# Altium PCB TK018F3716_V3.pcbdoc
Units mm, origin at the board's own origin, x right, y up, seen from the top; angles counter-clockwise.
Board outline 35.7 x 43.6 mm, 2 copper layers (Top Layer, Bottom Layer), stack 1.58 mm thick; 15 components, 14 nets, 81 pads, 72 vias.
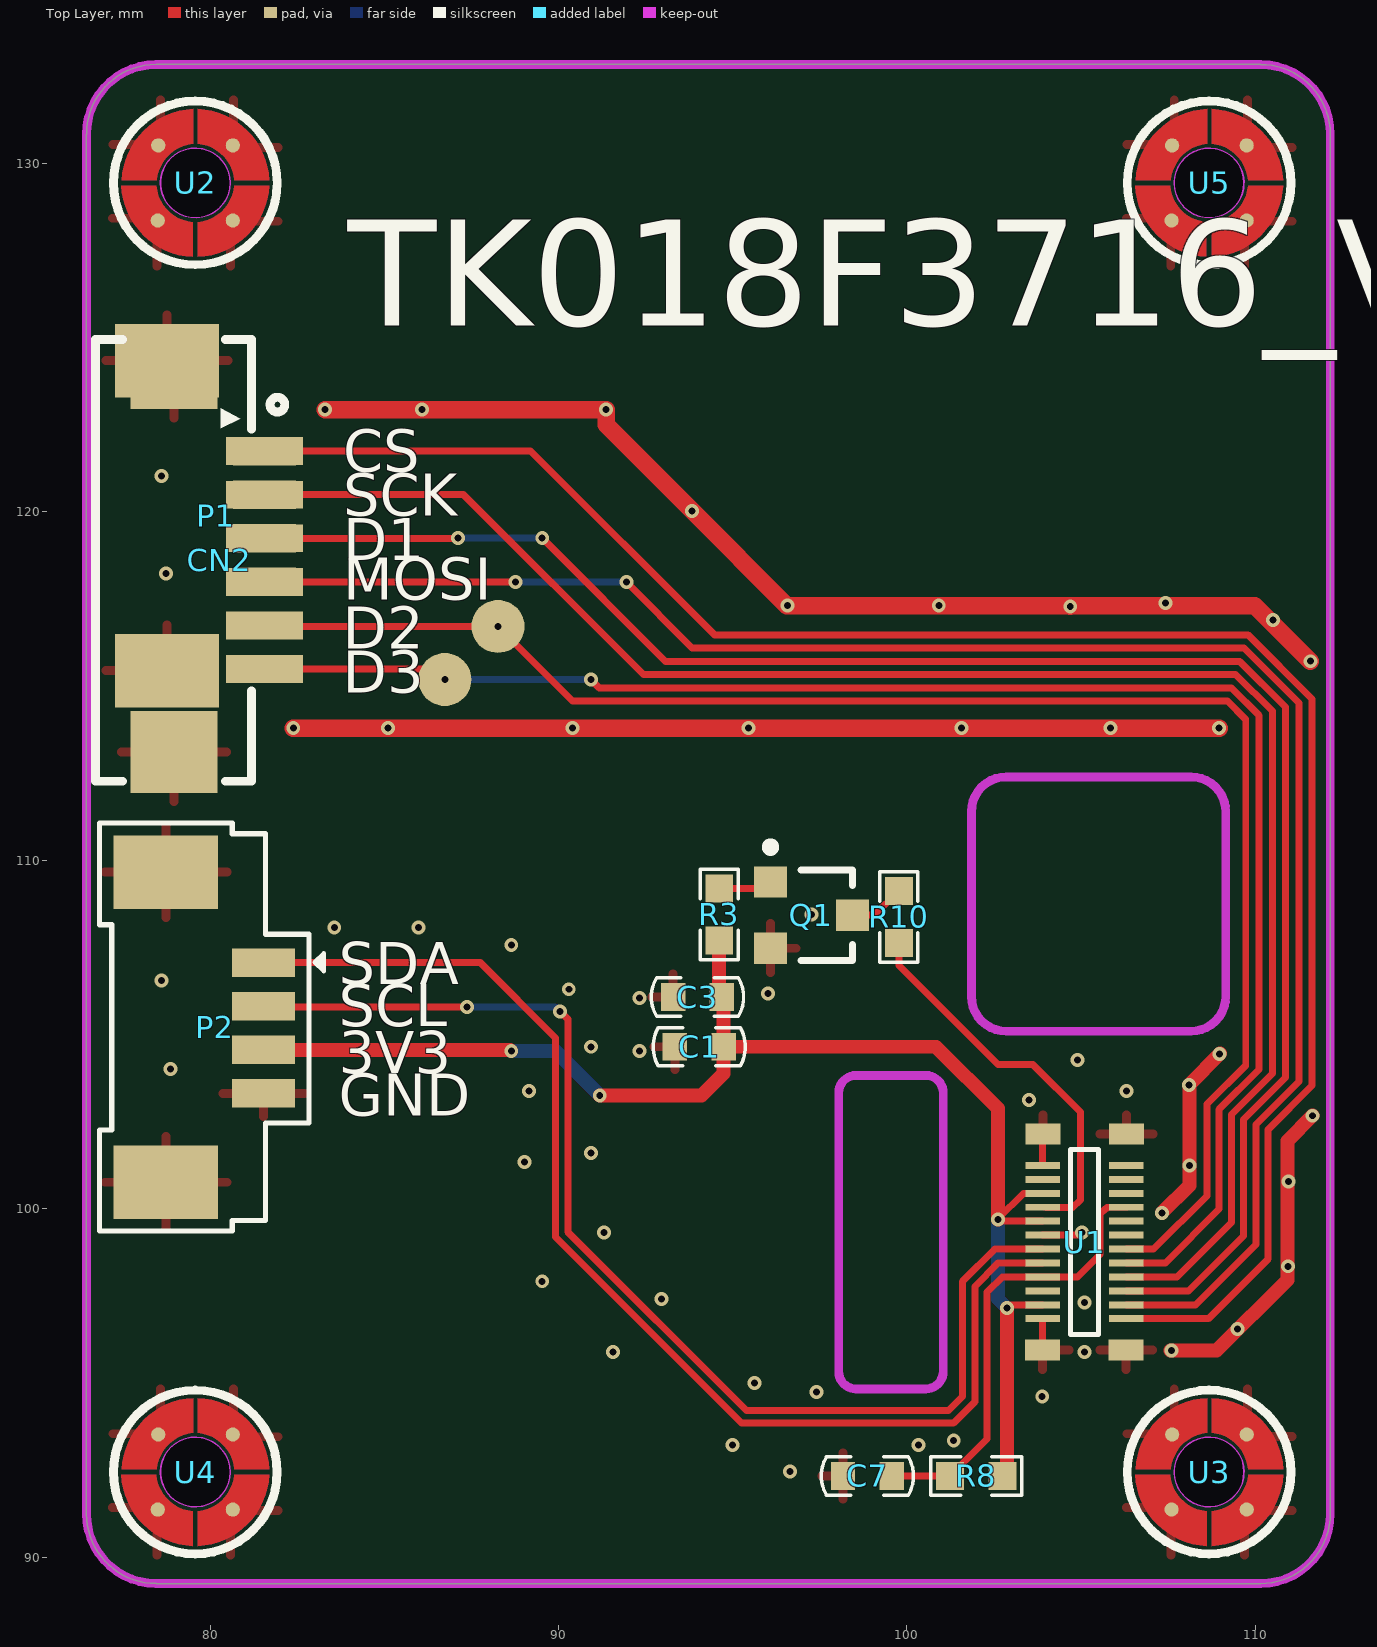
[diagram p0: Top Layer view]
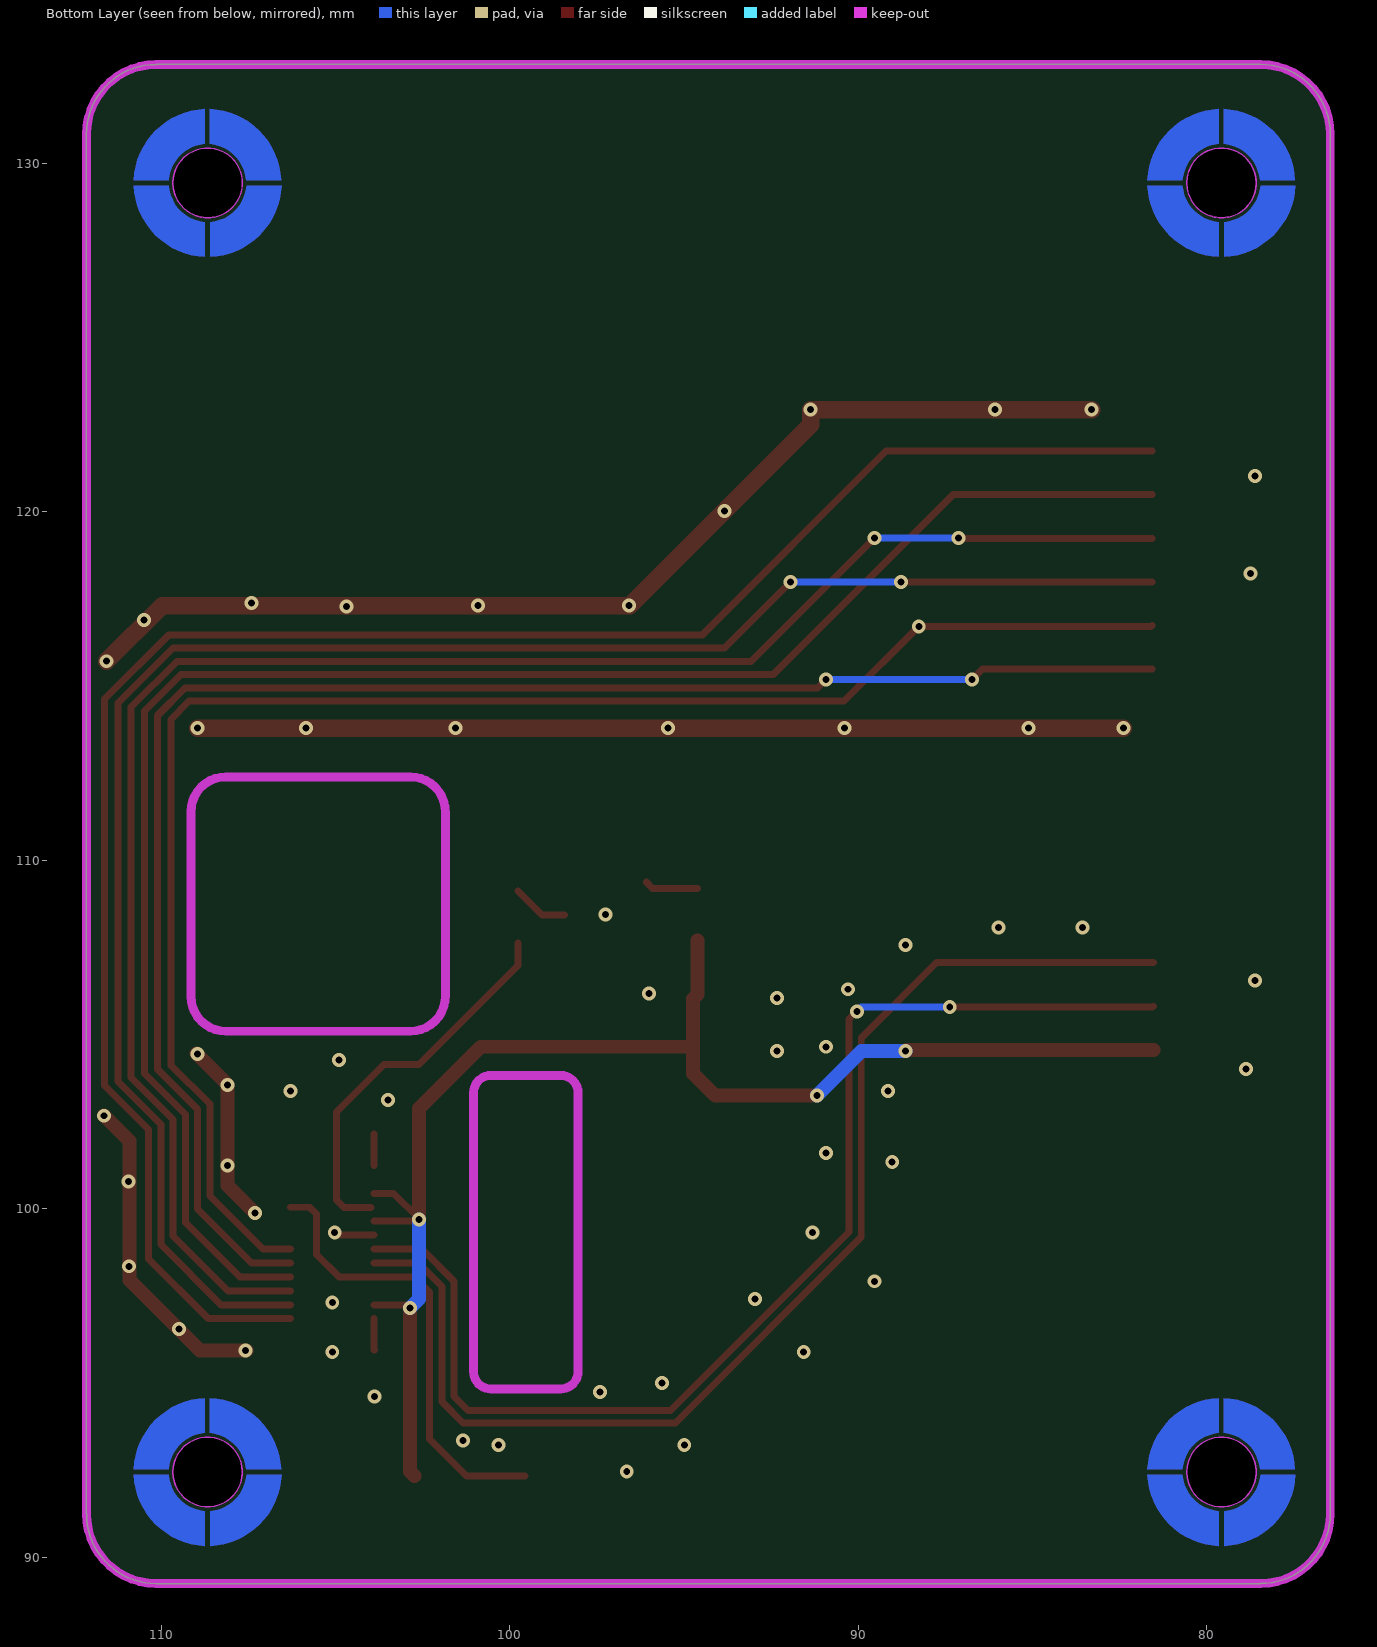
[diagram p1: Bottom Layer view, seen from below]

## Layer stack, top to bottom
Top Solder Mask Layer: solder mask 0.01, Dk 3.3
Top Layer: signal copper 0.035
Dielectric1: surface 1.51, FR4, Dk 4.5
Bottom Layer: signal copper 0.035
Bottom Solder Mask Layer: solder mask 0.01, Dk 3.3

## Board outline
78.454,132.842 ccw(c78.454,130.842) 76.454,130.842 76.454,91.242 ccw(c78.454,91.242) 78.454,89.242 110.154,89.242 ccw(c110.154,91.242) 112.154,91.242 112.154,130.842 ccw(c110.154,130.842) 110.154,132.842 78.454,132.842

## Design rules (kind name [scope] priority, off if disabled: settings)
BoardOutlineClearance copperThickness1oz [All] p0: genericclearance=0.254 ignorepadtopadclearanceinfootprint=FALSE except(0: Arc-SplitContinuation Track-SplitContinuation SMDPad-SplitContinuation THPad-SplitContinuation Via-SplitContinuation Fill-SplitContinuation Poly-SplitContinuation Region-SplitContinuation Text-SplitContinuation)
BoardOutlineClearance copperThickness2oz [All] p0: genericclearance=0.254 ignorepadtopadclearanceinfootprint=FALSE except(0: Arc-SplitContinuation Track-SplitContinuation SMDPad-SplitContinuation THPad-SplitContinuation Via-SplitContinuation Fill-SplitContinuation Poly-SplitContinuation Region-SplitContinuation Text-SplitContinuation)
BoardOutlineClearance otherClearance [All] p0: genericclearance=0.254 ignorepadtopadclearanceinfootprint=FALSE except(0: Arc-SplitContinuation Track-SplitContinuation SMDPad-SplitContinuation THPad-SplitContinuation Via-SplitContinuation Fill-SplitContinuation Poly-SplitContinuation Region-SplitContinuation Text-SplitContinuation)
Clearance copperThickness1oz [All] p1: gap=0.178 ignorepadtopadclearanceinfootprint=FALSE
Clearance copperThickness2oz [All] p1: gap=0.178 ignorepadtopadclearanceinfootprint=FALSE
Clearance otherClearance [All] p1: gap=0.178 ignorepadtopadclearanceinfootprint=FALSE
DiffPairsRouting differentialPair [All] p1: maxuncoupledlength=10 minlimit=6 maxlimit=Infinity mostfreqgap=6 toplayer_minwidth=5 toplayer_prefwidth=10 toplayer_maxwidth=100 bottomlayer_minwidth=5 bottomlayer_prefwidth=10 bottomlayer_maxwidth=100
PasteMaskExpansion pasteMaskExpansion [All] p1: expansion=0
PlaneConnect innerPlane [All] p1: planeconnectstyle=Relief reliefexpansion=0.508 reliefentries=4 reliefconductorwidth=0.254 reliefairgap=0.254
PolygonConnect copperRegion [All] p1: connectstyle=Relief reliefentries=4 reliefconductorwidth=10 polygonreliefangle="90 Angle" airgapwidth=10
RoutingVias viaSize [All] p1: viastyle="Through Hole" holewidth=7.874 minholewidth=7.874 maxholewidth=248.0314 width=7.874 minwidth=7.874 maxwidth=248.0314
SolderMaskExpansion solderMaskExpansion [IsVia] p1: useseparateexpansions=TRUE expansion=-1000 expansionbottom=-1000
SolderMaskExpansion solderMaskExpansion [All] p2: useseparateexpansions=TRUE expansion=2 expansionbottom=2
Width copperThickness1oz [All] p1: maxlimit=100 minlimit=5 preferedwidth=8
Width copperThickness2oz [All] p1: maxlimit=100 minlimit=8 preferedwidth=10

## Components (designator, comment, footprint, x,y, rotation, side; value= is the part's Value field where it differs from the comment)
C1 "104" C0603-1 94.742,104.648 r180 top
C3 "475" C0603-2 94.69,106.076 r180 top
C7 "104" C0603-1 99.568,92.329 r180 top
CN2 "HC-1.25-6PWT" CONN-SMD_6P-P1.25_HC-1.25-6PWT 80.264,118.618 r270 top
P1 "BHEADSMD1x4" BHEADSMD1x4 81.564,121.743 r90 top
P2 "BHEADSMD1x4" BHEADSMD1x4 81.534,107.061 r90 top
Q1 "SI2302" SOT23A 96.087,109.378 r270 top
R3 "18k" R0603 94.615,107.696 r90 top
R8 "18k" R0603 102.743,92.329 r180 top
R10 "5.1R" R0603 99.77,109.124 r270 top
U1 "" TK014F1246-24P 106.299,96.842 r270 top
U2 "" SMTWEM2 79.627,129.542 r0 top
U3 "" SMTWEM2 108.727,92.542 r0 top
U4 "" SMTWEM2 79.627,92.542 r0 top
U5 "" SMTWEM2 108.727,129.542 r0 top

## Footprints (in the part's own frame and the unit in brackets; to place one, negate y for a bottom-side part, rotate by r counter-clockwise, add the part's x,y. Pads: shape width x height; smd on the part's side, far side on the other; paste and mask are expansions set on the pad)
BHEADSMD1x4 [mil]
  rect 32x71 smd: 1(0,0) 2(-49.21,0) 3(-98.43,0) 4(-147.64,0)
  rect 83x118 smd: 5(102.36,110.24) 6(-248.03,110.24)
C0603-1 [mm]
  rect 0.7x0.8 smd paste+0.102 mask+0.1: 1(0,0) 2(1.4,0)
  silkscreen extent -0.62,-0.55 2.02,0.55
C0603-2 [mm]
  rect 0.7x0.8 smd paste+0.102 mask+0.1: 1(0,0) 2(1.4,0)
  silkscreen extent -0.62,-0.55 2.02,0.55
CONN-SMD_6P-P1.25_HC-1.25-6PWT [mm]
  rect 0.8x2.2 smd paste+0 mask+0.05: 1(-3.125,1.3) 2(-1.875,1.3) 3(-0.625,1.3) 4(0.625,1.3) 5(1.875,1.3) 6(3.125,1.3)
  rect 2.35x2.5 smd paste+0 mask+0.05: 7(-5.505,-1.3) 8(5.505,-1.3)
  silkscreen extent -6.33,-3.56 6.35,1.88
R0603 [mm]
  rect 0.8x0.8 smd paste+0.102 mask+0.1: 1(0,0) 2(1.5,0)
  silkscreen extent -0.55,-0.55 2.05,0.55
SMTWEM2 [mm]
  round 0.409 smd: 2(-1.127,-1.177) 2(-1.112,0.977) 2(1.027,-1.177) 2(1.027,0.977)
  Top Layer region: -2.159,-0.024 -2.14,0.174 -2.104,0.369 -2.049,0.56 -1.978,0.745 -1.889,0.923 -1.785,1.091 -1.665,1.25 -1.531,1.396 -1.385,1.53 -1.226,1.65 -1.057,1.754 -0.88,1.843 -0.695,1.915 -0.504,1.969 -0.309,2.005 -0.111,2.024 -0.111,1.022 -0.26,0.999 -0.404,0.957 -0.542,0.897 -0.671,0.819 -0.788,0.724 -0.887,0.622 -0.972,0.508 -1.043,0.385 -1.098,0.254 -1.136,0.117 -1.157,-0.024 -2.159,-0.024
  Top Layer region: 0.026,2.024 0.224,2.005 0.419,1.969 0.61,1.915 0.795,1.843 0.973,1.754 1.141,1.65 1.3,1.53 1.446,1.396 1.58,1.25 1.7,1.091 1.804,0.923 1.893,0.745 1.965,0.56 2.019,0.369 2.055,0.174 2.074,-0.024 1.072,-0.024 1.049,0.125 1.007,0.27 0.947,0.407 0.869,0.536 0.774,0.654 0.672,0.752 0.558,0.837 0.435,0.908 0.304,0.963 0.167,1.001 0.026,1.022 0.026,2.024
  Top Layer region: -0.126,-2.224 -0.324,-2.205 -0.519,-2.169 -0.71,-2.115 -0.895,-2.043 -1.073,-1.954 -1.241,-1.85 -1.4,-1.73 -1.546,-1.596 -1.68,-1.45 -1.8,-1.291 -1.904,-1.123 -1.993,-0.945 -2.065,-0.76 -2.119,-0.569 -2.155,-0.374 -2.174,-0.176 -1.172,-0.176 -1.149,-0.325 -1.107,-0.47 -1.047,-0.607 -0.969,-0.736 -0.874,-0.854 -0.772,-0.952 -0.658,-1.037 -0.535,-1.108 -0.404,-1.163 -0.267,-1.201 -0.126,-1.222 -0.126,-2.224
  Top Layer region: 2.074,-0.176 2.055,-0.374 2.019,-0.569 1.965,-0.76 1.893,-0.945 1.804,-1.123 1.7,-1.291 1.58,-1.45 1.446,-1.596 1.3,-1.73 1.141,-1.85 0.973,-1.954 0.795,-2.043 0.61,-2.115 0.419,-2.169 0.224,-2.205 0.026,-2.224 0.026,-2.224 0.026,-1.222 0.026,-1.222 0.175,-1.199 0.32,-1.157 0.457,-1.097 0.586,-1.019 0.704,-0.924 0.704,-0.924 0.802,-0.822 0.887,-0.708 0.958,-0.585 1.013,-0.454 1.051,-0.317 1.072,-0.176 1.072,-0.176 2.074,-0.176
  Bottom Layer region: -2.159,-0.024 -2.14,0.174 -2.104,0.369 -2.049,0.56 -1.978,0.745 -1.889,0.923 -1.785,1.091 -1.665,1.25 -1.531,1.396 -1.385,1.53 -1.226,1.65 -1.057,1.754 -0.88,1.843 -0.695,1.915 -0.504,1.969 -0.309,2.005 -0.111,2.024 -0.111,1.022 -0.26,0.999 -0.404,0.957 -0.542,0.897 -0.671,0.819 -0.788,0.724 -0.887,0.622 -0.972,0.508 -1.043,0.385 -1.098,0.254 -1.136,0.117 -1.157,-0.024 -2.159,-0.024
  Bottom Layer region: 0.026,2.024 0.224,2.005 0.419,1.969 0.61,1.915 0.795,1.843 0.973,1.754 1.141,1.65 1.3,1.53 1.446,1.396 1.58,1.25 1.7,1.091 1.804,0.923 1.893,0.745 1.965,0.56 2.019,0.369 2.055,0.174 2.074,-0.024 1.072,-0.024 1.049,0.125 1.007,0.27 0.947,0.407 0.869,0.536 0.774,0.654 0.672,0.752 0.558,0.837 0.435,0.908 0.304,0.963 0.167,1.001 0.026,1.022 0.026,2.024
  Bottom Layer region: -0.126,-2.224 -0.324,-2.205 -0.519,-2.169 -0.71,-2.115 -0.895,-2.043 -1.073,-1.954 -1.241,-1.85 -1.4,-1.73 -1.546,-1.596 -1.68,-1.45 -1.8,-1.291 -1.904,-1.123 -1.993,-0.945 -2.065,-0.76 -2.119,-0.569 -2.155,-0.374 -2.174,-0.176 -1.172,-0.176 -1.149,-0.325 -1.107,-0.47 -1.047,-0.607 -0.969,-0.736 -0.874,-0.854 -0.772,-0.952 -0.658,-1.037 -0.535,-1.108 -0.404,-1.163 -0.267,-1.201 -0.126,-1.222 -0.126,-2.224
  Bottom Layer region: 2.074,-0.176 2.055,-0.374 2.019,-0.569 1.965,-0.76 1.893,-0.945 1.804,-1.123 1.7,-1.291 1.58,-1.45 1.446,-1.596 1.3,-1.73 1.141,-1.85 0.973,-1.954 0.795,-2.043 0.61,-2.115 0.419,-2.169 0.224,-2.205 0.026,-2.224 0.026,-2.224 0.026,-1.222 0.026,-1.222 0.175,-1.199 0.32,-1.157 0.457,-1.097 0.586,-1.019 0.704,-0.924 0.704,-0.924 0.802,-0.822 0.887,-0.708 0.958,-0.585 1.013,-0.454 1.051,-0.317 1.072,-0.176 1.072,-0.176 2.074,-0.176
  Board Outline Layer circle w0.003: c-0.05,-0.1 r1
  Board Outline Layer region: 0.95,-0.1 0.852,-0.534 0.574,-0.882 0.173,-1.076 -0.273,-1.076 -0.674,-0.882 -0.952,-0.534 -1.051,-0.1 -1.05,-0.1 -0.952,0.334 -0.674,0.682 -0.273,0.876 0.173,0.876 0.574,0.682 0.852,0.334 0.951,-0.1
  Board Outline Layer region: 0.95,-0.1 0.941,-0.236 0.913,-0.37 0.867,-0.498 0.804,-0.62 0.726,-0.731 0.633,-0.831 0.527,-0.917 0.41,-0.988 0.285,-1.042 0.153,-1.079 0.018,-1.098 -0.118,-1.098 -0.253,-1.079 -0.385,-1.042 -0.51,-0.988 -0.627,-0.917 -0.733,-0.831 -0.826,-0.731 -0.904,-0.62 -0.967,-0.498 -1.013,-0.37 -1.041,-0.236 -1.05,-0.1 -1.041,0.036 -1.013,0.17 -0.967,0.298 -0.904,0.42 -0.826,0.531 -0.733,0.631 -0.627,0.717 -0.51,0.788 -0.385,0.842 -0.253,0.879 -0.118,0.898 0.018,0.898 0.153,0.879 0.285,0.842 0.41,0.788 0.527,0.717 0.633,0.631 0.726,0.531 0.804,0.42 0.867,0.298 0.913,0.17 0.941,0.036
  Multi-Layer region: -2.159,-0.024 -2.14,0.174 -2.104,0.369 -2.049,0.56 -1.978,0.745 -1.889,0.923 -1.785,1.091 -1.665,1.25 -1.531,1.396 -1.385,1.53 -1.226,1.65 -1.057,1.754 -0.88,1.843 -0.695,1.915 -0.504,1.969 -0.309,2.005 -0.111,2.024 -0.111,1.022 -0.26,0.999 -0.404,0.957 -0.542,0.897 -0.671,0.819 -0.788,0.724 -0.887,0.622 -0.972,0.508 -1.043,0.385 -1.098,0.254 -1.136,0.117 -1.157,-0.024 -2.159,-0.024
  Multi-Layer region: 0.026,2.024 0.224,2.005 0.419,1.969 0.61,1.915 0.795,1.843 0.973,1.754 1.141,1.65 1.3,1.53 1.446,1.396 1.58,1.25 1.7,1.091 1.804,0.923 1.893,0.745 1.965,0.56 2.019,0.369 2.055,0.174 2.074,-0.024 1.072,-0.024 1.049,0.125 1.007,0.27 0.947,0.407 0.869,0.536 0.774,0.654 0.672,0.752 0.558,0.837 0.435,0.908 0.304,0.963 0.167,1.001 0.026,1.022 0.026,2.024
  Multi-Layer region: -0.126,-2.224 -0.324,-2.205 -0.519,-2.169 -0.71,-2.115 -0.895,-2.043 -1.073,-1.954 -1.241,-1.85 -1.4,-1.73 -1.546,-1.596 -1.68,-1.45 -1.8,-1.291 -1.904,-1.123 -1.993,-0.945 -2.065,-0.76 -2.119,-0.569 -2.155,-0.374 -2.174,-0.176 -1.172,-0.176 -1.149,-0.325 -1.107,-0.47 -1.047,-0.607 -0.969,-0.736 -0.874,-0.854 -0.772,-0.952 -0.658,-1.037 -0.535,-1.108 -0.404,-1.163 -0.267,-1.201 -0.126,-1.222 -0.126,-2.224
  Multi-Layer region: 2.074,-0.176 2.055,-0.374 2.019,-0.569 1.965,-0.76 1.893,-0.945 1.804,-1.123 1.7,-1.291 1.58,-1.45 1.446,-1.596 1.3,-1.73 1.141,-1.85 0.973,-1.954 0.795,-2.043 0.61,-2.115 0.419,-2.169 0.224,-2.205 0.026,-2.224 0.026,-2.224 0.026,-1.222 0.026,-1.222 0.175,-1.199 0.32,-1.157 0.457,-1.097 0.586,-1.019 0.704,-0.924 0.704,-0.924 0.802,-0.822 0.887,-0.708 0.958,-0.585 1.013,-0.454 1.051,-0.317 1.072,-0.176 1.072,-0.176 2.074,-0.176
  Multi-Layer board cut-out: 0.95,-0.1 0.852,-0.534 0.574,-0.882 0.173,-1.076 -0.273,-1.076 -0.674,-0.882 -0.952,-0.534 -1.051,-0.1 -1.05,-0.1 -0.952,0.334 -0.674,0.682 -0.273,0.876 0.173,0.876 0.574,0.682 0.852,0.334 0.951,-0.1
  silkscreen extent -2.4,-2.45 2.3,2.25
SOT23A [mm]
  rect 0.9x0.95 smd: 1(0,0) 2(1.9,0) 3(0.95,2.35)
  silkscreen extent -1.12,-0.12 2.25,2.35
TK014F1246-24P [mm]
  rect 0.2x1 smd: 1(0,0) 2(-0.4,0) 3(-0.8,0) 4(-1.2,0) 5(-1.6,0) 6(-2,0) 7(-2.4,0) 8(-2.8,0) 9(-3.2,0) 10(-3.6,0) 11(-4,0) 12(-4.4,0) 13(-4.4,-2.4) 14(-4,-2.4) 15(-3.6,-2.4) 16(-3.2,-2.4) 17(-2.8,-2.4) 18(-2.4,-2.4) 19(-2,-2.4) 20(-1.6,-2.4) 21(-1.2,-2.4) 22(-0.8,-2.4) 23(-0.4,-2.4) 24(0,-2.4)
  rect 0.6x1 smd: 25(-5.3,0.006) 25(-5.3,-2.394) 25(0.9,-0.006) 25(0.9,-2.406)
  silkscreen extent -4.85,-1.6 0.45,-0.8

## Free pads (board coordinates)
  round 1.524 smd: 1(88.265,116.713) 2(86.741,115.189)

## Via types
v1: diameter 0.4, hole 0.201, Top Layer to Bottom Layer, 72 vias

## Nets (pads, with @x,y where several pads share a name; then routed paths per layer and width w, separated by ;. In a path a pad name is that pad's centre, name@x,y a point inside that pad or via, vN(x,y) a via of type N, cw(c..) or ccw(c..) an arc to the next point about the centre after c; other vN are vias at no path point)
3.3V: C1.1 C3.1 P2.3 R3.1 R8.1 U1.15 U1.17 U1.23 | length 41.1
  Top Layer w0.2: v1(102.616,99.695) 102.669,99.642 U1.17 ; v1@102.616,99.715 103.343,100.442 U1.15 ; v1(102.87,97.155) 102.957,97.242 U1.23
  Top Layer w0.4: P2.3 88.606,104.561 v1(88.646,104.521) ; v1(91.186,103.251) 94.107,103.251 94.742,103.886 C1.1 ; R3.1 94.615,106.151 C3.1 94.742,106.024 C1.1 ; v1(102.616,99.695) 102.616,99.715 102.616,102.87 100.838,104.648 C1.1 ; R8.1 102.87,92.456 v1(102.87,97.155)
  Bottom Layer w0.4: v1(88.646,104.521) 89.916,104.521 v1(91.186,103.251) ; v1(102.616,99.695) 102.616,97.409 v1(102.87,97.155)
$1N2: Q1.3 R10.1 | length 1.6
  Top Layer w0.2: Q1.3 99.074,108.428 R10.1
BL_CTR: Q1.1 R3.2 | length 1.5
  Top Layer w0.2: R3.2 95.906,109.196 Q1.1
CS: CN2.1 P1.1 U1.1 | length 54.4
  Top Layer w0.2: CN2.1 89.204,121.743 94.474,116.473 109.79,116.473 111.633,114.63 111.633,103.531 110.373,102.271 110.373,98.562 108.653,96.842 U1.1
GND: C1.2 C3.2 C7.2 CN2.7 CN2.8 P1.5 P1.6 P2.4 P2.5 P2.6 Q1.2 U1.13 U1.18 U1.24 U1.25 U2.2 U3.2 U4.2 U5.2 | length 76.3
  Top Layer w0.2: U1.25@103.893,95.942 103.899,95.948 U1.24 ; U1.18 104.957,99.242 v1(105.029,99.314) ; U1.13 103.899,102.136 U1.25@103.905,102.142
  Top Layer w0.4: v1@107.32,99.88 v1@107.327,99.887 ; v1@107.327,99.894 v1@107.327,99.887 ; v1@107.561,95.927 108.895,95.927 110.922,97.954 110.922,101.946 v1@111.65,102.674 ; v1@108.993,104.454 108.107,103.568 108.107,100.668 v1@107.327,99.887
  Top Layer w0.5: v1(82.389,113.792) v1(85.114,113.792) v1(90.401,113.792) v1(95.461,113.792) v1(101.565,113.792) v1(105.851,113.792) v1(108.966,113.792) ; v1(83.302,122.936) v1(86.084,122.936) v1(91.371,122.936) 91.371,122.497 v1(93.837,120.03) ; v1(93.837,120.03) 96.559,117.308 v1(96.579,117.308) v1(100.917,117.309) 105.392,117.309 ; v1(104.69,117.287) 105.392,117.309 ; v1(111.58,115.714) 109.985,117.309 105.392,117.309
  other v1: 96.647,92.456 94.996,93.218 100.33,93.218 101.346,93.345 103.886,94.615 97.409,94.742 95.631,94.996 91.567,95.885 105.099,95.881 107.593,95.928 109.493,96.545 105.099,97.305 92.964,97.409 89.535,97.917 110.935,98.348 91.313,99.314 107.32,99.879 110.949,100.775 108.111,101.245 89.027,101.346 90.932,101.6 111.649,102.668 103.505,103.124 89.154,103.378 106.299,103.378 108.104,103.547 78.867,104.013 104.902,104.267 108.971,104.434 92.329,104.521 90.932,104.648 92.329,106.045 96.012,106.172 90.297,106.299 78.613,106.553 88.646,107.569 83.566,108.077 85.979,108.077 97.262,108.44 110.504,116.895 107.422,117.38 78.74,118.237 78.613,121.031
LED-: R10.2 U1.16 | length 11.2
  Top Layer w0.2: R10.2 99.77,106.986 102.614,104.142 103.615,104.142 104.98,102.776 104.98,100.255 104.758,100.033 U1.16@103.982,100.033
MOSI: CN2.4 P1.4 U1.2 | length 51.6
  Top Layer w0.2: CN2.4 88.763,117.993 v1(88.773,117.983) ; v1(91.948,117.983) 93.839,116.092 109.673,116.092 111.252,114.513 111.252,103.648 110.021,102.416 110.021,98.972 108.291,97.242 U1.2
  Bottom Layer w0.2: v1(88.773,117.983) v1(91.948,117.983)
QSPI_D1: CN2.3 P1.3 U1.3 | length 51
  Top Layer w0.2: CN2.3 87.112,119.243 v1(87.122,119.253) ; v1(89.535,119.253) 93.077,115.711 109.556,115.711 110.871,114.396 110.871,103.764 109.669,102.562 109.669,99.221 108.09,97.642 U1.3
  Bottom Layer w0.2: v1(87.122,119.253) v1(89.535,119.253)
QSPI_D2: CN2.5 pad.1 U1.6 | length 46.4
  Top Layer w0.2: CN2.5 81.594,116.713 v1(88.265,116.713) 90.41,114.568 109.206,114.568 109.728,114.046 109.728,104.115 108.613,103 108.613,100.369 107.086,98.842 U1.6
QSPI_D3: CN2.6 pad.2 U1.5 | length 47.1
  Top Layer w0.2: CN2.6 86.437,115.493 v1(86.741,115.189) ; v1(90.932,115.189) 91.172,114.949 109.322,114.949 110.109,114.163 110.109,103.998 108.965,102.854 108.965,99.988 107.419,98.442 U1.5
  Bottom Layer w0.2: v1(86.741,115.189) v1(90.932,115.189)
RST: C7.1 R8.2 U1.9 U1.21 | length 13.1
  Top Layer w0.2: C7.1 R8.2 102.304,93.39 102.304,97.605 102.741,98.042 U1.21 104.9,98.042 105.547,98.689 105.547,99.846 105.695,99.994 105.709,99.994 105.757,100.042 U1.9
SCK: CN2.2 P1.2 U1.4 | length 50.3
  Top Layer w0.2: CN2.2 87.279,120.493 92.442,115.33 109.439,115.33 110.49,114.28 110.49,103.881 109.317,102.708 109.317,99.607 107.752,98.042 U1.4
SCL: P2.2 U1.19 | length 34.6
  Top Layer w0.2: P2.2 81.554,105.791 v1(87.376,105.791) ; v1(90.043,105.664) 90.268,105.439 90.268,99.333 95.396,94.205 101.2,94.205 101.6,94.605 101.6,97.917 102.525,98.842 U1.19
  Bottom Layer w0.2: v1(87.376,105.791) 89.916,105.791 v1(90.043,105.664)
SDA: P2.1 U1.20 | length 35
  Top Layer w0.2: P2.1 87.757,107.061 89.916,104.902 89.916,99.187 95.25,93.853 101.346,93.853 101.952,94.459 101.952,97.771 102.623,98.442 U1.20
pads on no net: U1.7 U1.8 U1.10 U1.11 U1.12 U1.14 U1.22

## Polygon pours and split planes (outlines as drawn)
GND on Top Layer (solid, remove dead copper, pour order 0): 76.2,132.969 76.2,88.773 112.522,88.773 112.522,132.969
GND on Bottom Layer (solid, remove dead copper, pour order 2): 76.2,132.969 76.2,88.773 112.522,88.773 112.522,132.969

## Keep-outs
Board Outline Layer:
  lines w0.254: 76.454,91.242 76.454,130.842 cw(c78.454,130.842) 78.454,132.842 110.154,132.842 cw(c110.154,130.842) 112.154,130.842 112.154,91.242 cw(c110.154,91.242) 110.154,89.242 78.454,89.242 cw(c78.454,91.242) 76.454,91.242 ; 76.454,91.242 76.454,91.242 ; 98.044,95.327 98.044,103.327 cw(c98.544,103.327) 98.544,103.827 100.544,103.827 cw(c100.544,103.327) 101.044,103.327 101.044,95.327 ; 98.044,95.327 98.044,95.327 ; 98.044,95.327 ccw(c98.544,95.327) 98.544,94.827 100.544,94.827 ccw(c100.544,95.327) 101.044,95.327 ; 101.044,95.327 101.044,95.327 ; 101.854,106.095 101.854,111.395 cw(c102.854,111.395) 102.854,112.395 108.154,112.395 cw(c108.154,111.395) 109.154,111.395 109.154,106.095 cw(c108.154,106.095) 108.154,105.095 102.854,105.095 cw(c102.854,106.095) 101.854,106.095

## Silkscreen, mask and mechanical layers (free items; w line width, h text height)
Top Silkscreen Layer:
  text "TK018F3716_V3" at 83.947,125.349 h3.05
  text "CS" at 83.82,121.158 h1.2
  text "SCK" at 83.82,119.888 h1.2
  text "D1" at 83.82,118.618 h1.2
  text "MOSI" at 83.82,117.475 h1.2
  text "D2" at 83.809,116.078 h1.2
  text "D3" at 83.809,114.808 h1.2
  text "SDA" at 83.693,106.442 h1.2
  text "SCL" at 83.693,105.242 h1.2
  text "3V3" at 83.689,103.886 h1.2
  text "GND" at 83.693,102.673 h1.2

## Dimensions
122.301,132.842 to 122.301,89.242 on Document Layer
76.454,76.2 to 112.014,76.2 on Document Layer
